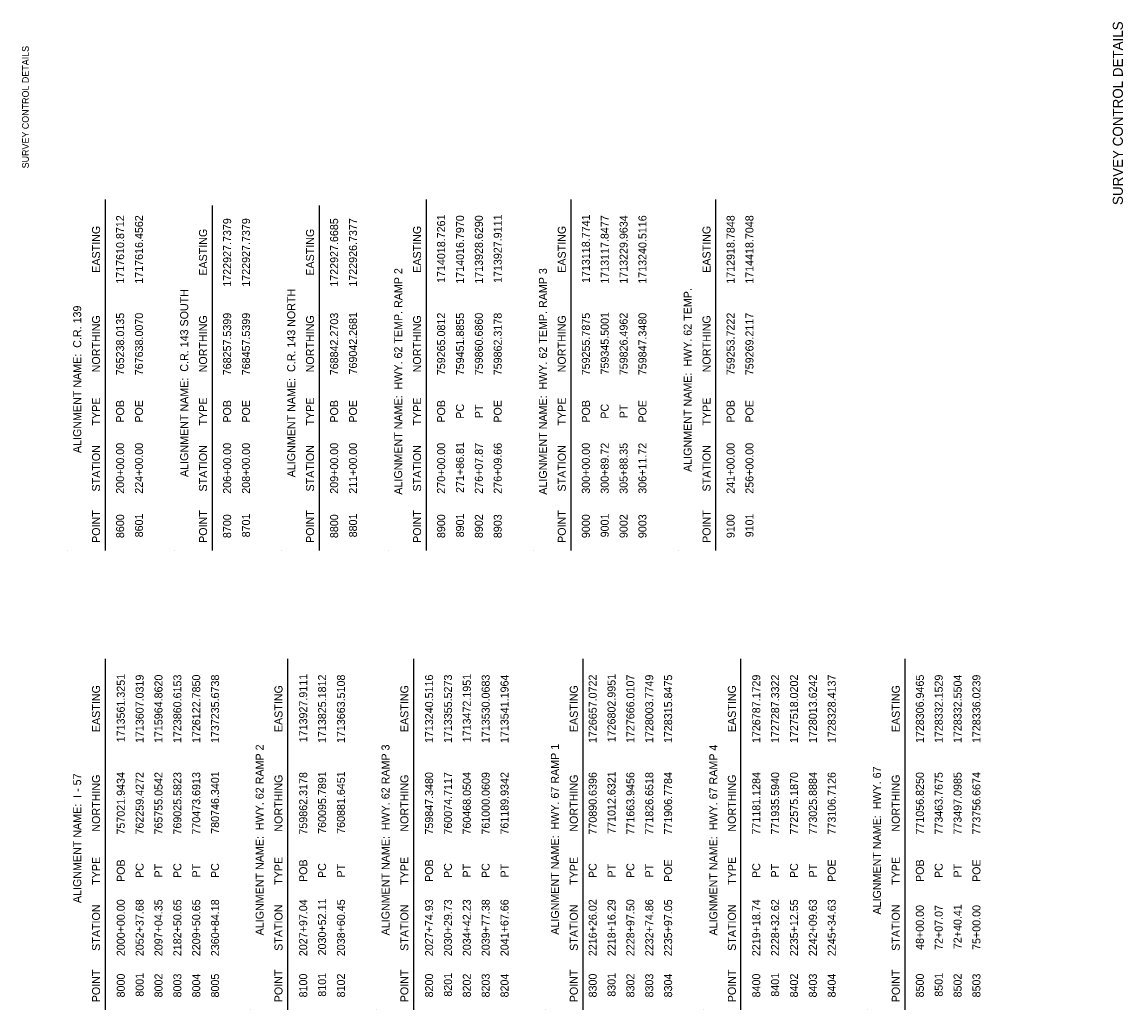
# Model space of a CAD drawing. Extents: x 1713392 to 1714382, y 756442 to 757988.
# Drawn here: x 1713392 to 1714382, y 757099 to 757988 of the extents above; entities that cross this region are included whole.
import ezdxf

# ---------------------------------------------------------------- set-up
doc = ezdxf.new("R2010")
doc.units = 0
doc.layers.add('Default', color=7, linetype='Continuous')
doc.layers.add('G-ANNO-TEXT', color=7, linetype='Continuous')

msp = doc.modelspace()

# ---------------------------------------------------------------- linework, layer by layer
at = {"layer": 'Default'}
for p, q in [((1713466.73, 757512.69), (1713466.73, 757828.59)), ((1713562.98, 757512.69), (1713562.98, 757823.32)), ((1713659.23, 757512.69), (1713659.23, 757823.32)), ((1713755.47, 757512.69), (1713755.47, 757828.59)), ((1713885.65, 757512.69), (1713885.65, 757828.59)), ((1714015.83, 757512.69), (1714015.83, 757828.59)), ((1713432.8, 757512.69), (1713432.8, 757512.69)), ((1713529.05, 757512.69), (1713529.05, 757512.69)), ((1713625.3, 757512.69), (1713625.3, 757512.69)), ((1713721.54, 757512.69), (1713721.54, 757512.69)), ((1713851.72, 757512.69), (1713851.72, 757512.69)), ((1713981.9, 757512.69), (1713981.9, 757512.69)), ((1713466.73, 757099.5), (1713466.73, 757415.4)), ((1713630.84, 757099.5), (1713630.84, 757415.4)), ((1713744.05, 757099.5), (1713744.05, 757415.4)), ((1713896.46, 757099.5), (1713896.46, 757415.4)), ((1714038.34, 757099.5), (1714038.34, 757415.4)), ((1714186.07, 757099.5), (1714186.07, 757415.4)), ((1713596.91, 757099.5), (1713596.91, 757099.5)), ((1713710.12, 757099.5), (1713710.12, 757099.5)), ((1713862.53, 757099.5), (1713862.53, 757099.5)), ((1714004.99, 757099.5), (1714004.99, 757099.5)), ((1714152.14, 757099.5), (1714152.14, 757099.5))]:
    msp.add_line(p, q, dxfattribs=at)

# ---------------------------------------------------------------- texts
for s, p in [('1717610.8712', (1713483.49, 757752.83)), ('1717616.4562', (1713500.46, 757752.83)), ('1722927.7379', (1713579.74, 757750.15)), ('1722927.7379', (1713596.7, 757750.15)), ('1722927.6685', (1713675.99, 757750.13)), ('1722926.7377', (1713692.95, 757750.16)), ('1714018.7261', (1713772.24, 757753.49)), ('1714016.7970', (1713789.2, 757752.8)), ('1713928.6290', (1713806.17, 757752.8)), ('1713927.9111', (1713823.13, 757753.49)), ('1713118.7741', (1713902.42, 757753.49)), ('1713117.8477', (1713919.38, 757752.79)), ('1713229.9634', (1713936.35, 757752.8)), ('1713240.5116', (1713953.31, 757752.79)), ('1712918.7848', (1714032.59, 757752.78)), ('1714418.7048', (1714049.56, 757752.78)), ('EASTING', (1713461.85, 757762.66)), ('EASTING', (1713558.09, 757760.03)), ('EASTING', (1713654.34, 757760.03)), ('EASTING', (1713750.59, 757762.66)), ('EASTING', (1713880.77, 757762.66)), ('EASTING', (1714010.95, 757762.66)), ('ALIGNMENT NAME:  HWY. 62 TEMP. RAMP 2', (1713733.63, 757563.03)), ('ALIGNMENT NAME:  HWY. 62 TEMP. RAMP 3', (1713863.81, 757562.99)), ('ALIGNMENT NAME:  C.R. 143 SOUTH', (1713541.13, 757578.97)), ('ALIGNMENT NAME:  C.R. 143 NORTH', (1713637.38, 757578.69)), ('ALIGNMENT NAME:  HWY. 62 TEMP.', (1713993.98, 757583.52)), ('ALIGNMENT NAME:  C.R. 139', (1713444.88, 757600.45)), ('NORTHING', (1713461.85, 757673.07)), ('765238.0135', (1713483.49, 757670.44)), ('767638.0070', (1713500.46, 757670.48)), ('NORTHING', (1713558.09, 757673.07)), ('768257.5399', (1713579.74, 757670.46)), ('768457.5399', (1713596.7, 757670.46)), ('NORTHING', (1713654.34, 757673.07)), ('768842.2703', (1713675.99, 757670.47)), ('769042.2681', (1713692.95, 757671.16)), ('NORTHING', (1713750.59, 757673.07)), ('759265.0812', (1713772.24, 757670.51)), ('759451.8855', (1713789.2, 757670.44)), ('759860.6860', (1713806.17, 757670.48)), ('759862.3178', (1713823.13, 757670.46)), ('NORTHING', (1713880.77, 757673.07)), ('759255.7875', (1713902.42, 757670.44)), ('759345.5001', (1713919.38, 757671.16)), ('759826.4962', (1713936.35, 757670.51)), ('759847.3480', (1713953.31, 757670.48)), ('NORTHING', (1714010.95, 757673.07)), ('759253.7222', (1714032.59, 757670.51)), ('759269.2117', (1714049.56, 757670.47)), ('TYPE', (1713461.85, 757625.28)), ('POB', (1713483.49, 757627.82)), ('POE', (1713500.46, 757627.82)), ('TYPE', (1713558.09, 757625.28)), ('POB', (1713579.74, 757627.82)), ('POE', (1713596.7, 757627.82)), ('TYPE', (1713654.34, 757625.28)), ('POB', (1713675.99, 757627.82)), ('POE', (1713692.95, 757627.82)), ('TYPE', (1713750.59, 757625.28)), ('POB', (1713772.24, 757627.82)), ('PC', (1713789.2, 757631.38)), ('PT', (1713806.17, 757631.84)), ('POE', (1713823.13, 757627.82)), ('TYPE', (1713880.77, 757625.28)), ('POB', (1713902.42, 757627.82)), ('PC', (1713919.38, 757631.38)), ('PT', (1713936.35, 757631.84)), ('POE', (1713953.31, 757627.82)), ('TYPE', (1714010.95, 757625.28)), ('POB', (1714032.59, 757627.82)), ('POE', (1714049.56, 757627.82)), ('STATION', (1713461.85, 757565.89)), ('200+00.00', (1713483.49, 757563.91)), ('224+00.00', (1713500.46, 757563.91)), ('STATION', (1713558.09, 757565.89)), ('206+00.00', (1713579.74, 757563.91)), ('208+00.00', (1713596.7, 757563.91)), ('STATION', (1713654.34, 757565.89)), ('209+00.00', (1713675.99, 757563.91)), ('211+00.00', (1713692.95, 757563.91)), ('STATION', (1713750.59, 757565.89)), ('270+00.00', (1713772.24, 757563.91)), ('271+86.81', (1713789.2, 757564.59)), ('276+07.87', (1713806.17, 757563.89)), ('276+09.66', (1713823.13, 757563.89)), ('STATION', (1713880.77, 757565.89)), ('300+00.00', (1713902.42, 757563.91)), ('300+89.72', (1713919.38, 757563.93)), ('305+88.35', (1713936.35, 757563.86)), ('306+11.72', (1713953.31, 757563.93)), ('STATION', (1714010.95, 757565.89)), ('241+00.00', (1714032.59, 757563.91)), ('256+00.00', (1714049.56, 757563.91)), ('POINT', (1713461.85, 757519.65)), ('8600', (1713483.49, 757523.98)), ('8601', (1713500.46, 757524.66)), ('POINT', (1713558.09, 757519.65)), ('8700', (1713579.74, 757523.98)), ('8701', (1713596.7, 757524.66)), ('POINT', (1713654.34, 757519.65)), ('8800', (1713675.99, 757523.98)), ('8801', (1713692.95, 757524.66)), ('POINT', (1713750.59, 757519.65)), ('8900', (1713772.24, 757523.98)), ('8901', (1713789.2, 757524.66)), ('8902', (1713806.17, 757524)), ('8903', (1713823.13, 757523.96)), ('POINT', (1713880.77, 757519.65)), ('9000', (1713902.42, 757523.98)), ('9001', (1713919.38, 757524.66)), ('9002', (1713936.35, 757524)), ('9003', (1713953.31, 757523.96)), ('POINT', (1714010.95, 757519.65)), ('9100', (1714032.59, 757523.98)), ('9101', (1714049.56, 757524.66)), ('1713561.3251', (1713484.08, 757340.29)), ('1713607.0319', (1713501.04, 757339.59)), ('1715964.8620', (1713518.01, 757339.61)), ('1723860.6153', (1713534.97, 757339.6)), ('1726122.7850', (1713551.94, 757339.61)), ('1737235.6738', (1713568.9, 757339.59)), ('1713927.9111', (1713648.18, 757340.29)), ('1713825.1812', (1713665.15, 757339.64)), ('1713663.5108', (1713682.11, 757339.59)), ('1713240.5116', (1713761.4, 757339.6)), ('1713355.5273', (1713778.36, 757339.6)), ('1713472.1951', (1713795.33, 757340.29)), ('1713530.0683', (1713812.29, 757339.6)), ('1713541.1964', (1713829.26, 757339.61)), ('1726657.0722', (1713908.54, 757339.64)), ('1726802.9951', (1713925.51, 757340.29)), ('1727666.0107', (1713942.47, 757339.6)), ('1728003.7749', (1713959.44, 757339.59)), ('1728315.8475', (1713976.4, 757339.57)), ('1726787.1729', (1714055.69, 757339.59)), ('1727287.3322', (1714072.65, 757339.64)), ('1727518.0202', (1714089.62, 757339.64)), ('1728013.6242', (1714106.58, 757339.64)), ('1728328.4137', (1714123.55, 757339.6)), ('1728306.9465', (1714202.83, 757339.57)), ('1728332.1529', (1714219.79, 757339.59)), ('1728332.5504', (1714236.76, 757339.61)), ('1728336.0239', (1714253.72, 757339.59)), ('EASTING', (1713461.85, 757349.47)), ('EASTING', (1713625.95, 757349.47)), ('EASTING', (1713739.17, 757349.47)), ('EASTING', (1713891.58, 757349.47)), ('EASTING', (1714033.75, 757349.47)), ('EASTING', (1714181.18, 757349.47)), ('ALIGNMENT NAME:  HWY. 62 RAMP 2', (1713608.99, 757166.6)), ('ALIGNMENT NAME:  HWY. 62 RAMP 3', (1713722.2, 757166.57)), ('ALIGNMENT NAME:  HWY. 67 RAMP 1', (1713874.61, 757167.17)), ('ALIGNMENT NAME:  HWY. 67 RAMP 4', (1714017.08, 757166.47)), ('ALIGNMENT NAME:  HWY. 67 ', (1714164.22, 757185.35)), ('ALIGNMENT NAME:  I - 57', (1713444.88, 757195.64)), ('NORTHING', (1713461.85, 757259.88)), ('757021.9434', (1713484.08, 757257.29)), ('762259.4272', (1713501.04, 757257.31)), ('765755.0542', (1713518.01, 757257.31)), ('769025.5823', (1713534.97, 757257.28)), ('770473.6913', (1713551.94, 757257.28)), ('780746.3401', (1713568.9, 757257.97)), ('NORTHING', (1713625.95, 757259.88)), ('759862.3178', (1713648.18, 757257.27)), ('760095.7891', (1713665.15, 757257.97)), ('760881.6451', (1713682.11, 757257.97)), ('NORTHING', (1713739.17, 757259.88)), ('759847.3480', (1713761.4, 757257.29)), ('760074.7117', (1713778.36, 757257.28)), ('760468.0504', (1713795.33, 757257.29)), ('761000.0609', (1713812.29, 757257.27)), ('761189.9342', (1713829.26, 757257.31)), ('NORTHING', (1713891.58, 757259.88)), ('770890.6396', (1713908.54, 757257.28)), ('771012.6321', (1713925.51, 757257.97)), ('771663.9456', (1713942.47, 757257.28)), ('771826.6518', (1713959.44, 757257.27)), ('771906.7784', (1713976.4, 757257.29)), ('NORTHING', (1714033.75, 757259.88)), ('771181.1284', (1714055.69, 757257.29)), ('771935.5940', (1714072.65, 757257.29)), ('772575.1870', (1714089.62, 757257.29)), ('773025.8884', (1714106.58, 757257.29)), ('773106.7126', (1714123.55, 757257.28)), ('NORTHING', (1714181.18, 757259.88)), ('771056.8250', (1714202.83, 757257.29)), ('773463.7675', (1714219.79, 757257.25)), ('773497.0985', (1714236.76, 757257.25)), ('773756.6674', (1714253.72, 757257.29)), ('TYPE', (1713461.85, 757212.09)), ('TYPE', (1713625.95, 757212.09)), ('TYPE', (1713739.17, 757212.09)), ('TYPE', (1713891.58, 757212.09)), ('TYPE', (1714033.75, 757212.09)), ('TYPE', (1714181.18, 757212.09)), ('POB', (1713484.08, 757214.62)), ('PC', (1713501.04, 757218.19)), ('PT', (1713518.01, 757218.65)), ('PC', (1713534.97, 757218.19)), ('PT', (1713551.94, 757218.65)), ('PC', (1713568.9, 757218.19)), ('POB', (1713648.18, 757214.62)), ('PC', (1713665.15, 757218.19)), ('PT', (1713682.11, 757218.65)), ('POB', (1713761.4, 757214.62)), ('PC', (1713778.36, 757218.19)), ('PT', (1713795.33, 757218.65)), ('PC', (1713812.29, 757218.19)), ('PT', (1713829.26, 757218.65)), ('PC', (1713908.54, 757218.19)), ('PT', (1713925.51, 757218.65)), ('PC', (1713942.47, 757218.19)), ('PT', (1713959.44, 757218.65)), ('POE', (1713976.4, 757214.62)), ('PC', (1714055.69, 757218.19)), ('PT', (1714072.65, 757218.65)), ('PC', (1714089.62, 757218.19)), ('PT', (1714106.58, 757218.65)), ('POE', (1714123.55, 757214.62)), ('POB', (1714202.83, 757214.62)), ('PC', (1714219.79, 757218.19)), ('PT', (1714236.76, 757218.65)), ('POE', (1714253.72, 757214.62)), ('2000+00.00', (1713484.08, 757147.92)), ('2052+37.68', (1713501.04, 757147.9)), ('2097+04.35', (1713518.01, 757147.88)), ('2182+50.65', (1713534.97, 757147.88)), ('2209+50.65', (1713551.94, 757147.88)), ('2360+84.18', (1713568.9, 757147.9)), ('2027+97.04', (1713648.18, 757147.92)), ('2030+52.11', (1713665.15, 757148.6)), ('2038+60.45', (1713682.11, 757147.88)), ('2027+74.93', (1713761.4, 757147.9)), ('2030+29.73', (1713778.36, 757147.9)), ('2034+42.23', (1713795.33, 757147.9)), ('2039+77.38', (1713812.29, 757147.9)), ('2041+67.66', (1713829.26, 757147.9)), ('2216+26.02', (1713908.54, 757147.94)), ('2218+16.29', (1713925.51, 757147.9)), ('2228+97.50', (1713942.47, 757147.92)), ('2232+74.86', (1713959.44, 757147.9)), ('2235+97.05', (1713976.4, 757147.88)), ('2219+18.74', (1714055.69, 757147.92)), ('2228+32.62', (1714072.65, 757147.94)), ('2235+12.55', (1714089.62, 757147.88)), ('2242+09.63', (1714106.58, 757147.9)), ('2245+34.63', (1714123.55, 757147.9)), ('STATION', (1713461.85, 757152.7)), ('STATION', (1713625.95, 757152.7)), ('STATION', (1713739.17, 757152.7)), ('STATION', (1713891.58, 757152.7)), ('STATION', (1714033.75, 757152.7)), ('STATION', (1714181.18, 757152.7)), ('48+00.00', (1714202.83, 757153.51)), ('72+07.07', (1714219.79, 757153.5)), ('72+40.41', (1714236.76, 757154.19)), ('75+00.00', (1714253.72, 757153.51)), ('POINT', (1713461.85, 757106.46)), ('8000', (1713484.08, 757110.79)), ('8001', (1713501.04, 757111.47)), ('8002', (1713518.01, 757110.81)), ('8003', (1713534.97, 757110.77)), ('8004', (1713551.94, 757110.79)), ('8005', (1713568.9, 757110.74)), ('POINT', (1713625.95, 757106.46)), ('8100', (1713648.18, 757110.79)), ('8101', (1713665.15, 757111.47)), ('8102', (1713682.11, 757110.81)), ('POINT', (1713739.17, 757106.46)), ('8200', (1713761.4, 757110.79)), ('8201', (1713778.36, 757111.47)), ('8202', (1713795.33, 757110.81)), ('8203', (1713812.29, 757110.77)), ('8204', (1713829.26, 757110.79)), ('POINT', (1713891.58, 757106.46)), ('8300', (1713908.54, 757110.79)), ('8301', (1713925.51, 757111.47)), ('8302', (1713942.47, 757110.81)), ('8303', (1713959.44, 757110.77)), ('8304', (1713976.4, 757110.79)), ('POINT', (1714033.75, 757106.46)), ('8400', (1714055.69, 757110.79)), ('8401', (1714072.65, 757111.47)), ('8402', (1714089.62, 757110.81)), ('8403', (1714106.58, 757110.77)), ('8404', (1714123.55, 757110.79)), ('POINT', (1714181.18, 757106.46)), ('8500', (1714202.83, 757110.79)), ('8501', (1714219.79, 757111.47)), ('8502', (1714236.76, 757110.81)), ('8503', (1714253.72, 757110.77))]:
    msp.add_text(s, height=7.2, rotation=90, dxfattribs=at).set_placement(p)
at = {"layer": 'G-ANNO-TEXT'}
for height, p in [(9, (1714381.82, 757823.6)), (6, (1713397.74, 757856.6))]:
    msp.add_text('SURVEY CONTROL DETAILS', height=height, rotation=90, dxfattribs=at).set_placement(p)

doc.saveas('drawing.dxf')
